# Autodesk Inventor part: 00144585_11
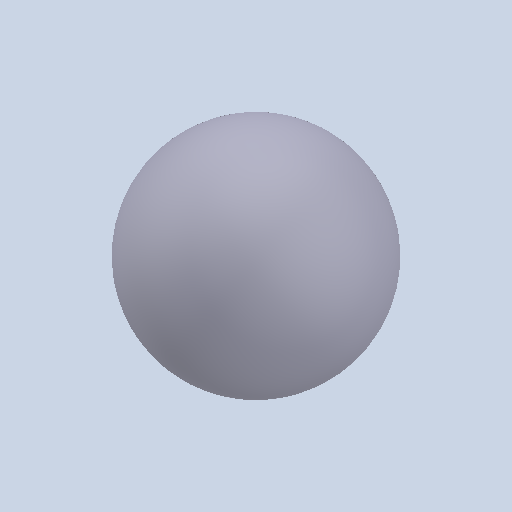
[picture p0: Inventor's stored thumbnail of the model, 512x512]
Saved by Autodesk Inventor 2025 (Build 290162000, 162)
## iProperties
Created: 2021-02
Part Number: 00144585_11
Material: Generico
Document SubType Name: Modeling
Designer: Ryzen5700u
Density: 1 g/cm^3
Appearance: Default
Author: Ryzen5700u
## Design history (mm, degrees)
feature "Solido1"
node "Solido2"
